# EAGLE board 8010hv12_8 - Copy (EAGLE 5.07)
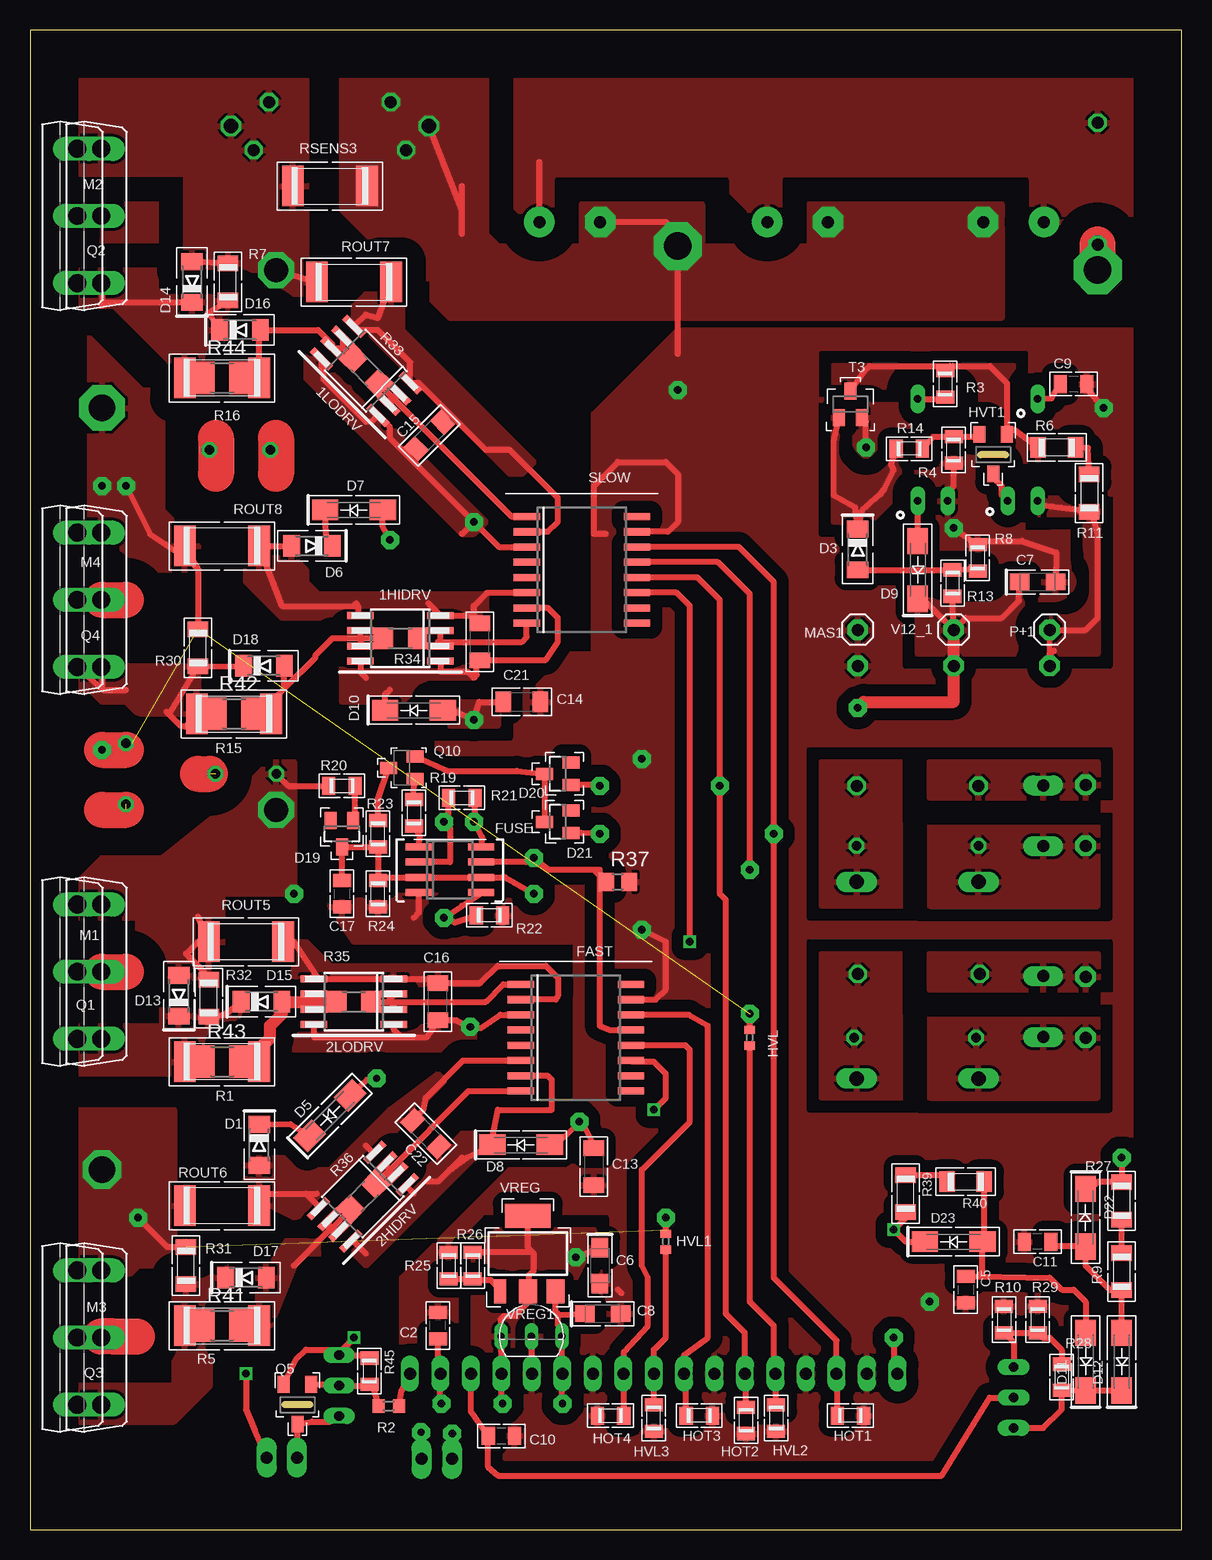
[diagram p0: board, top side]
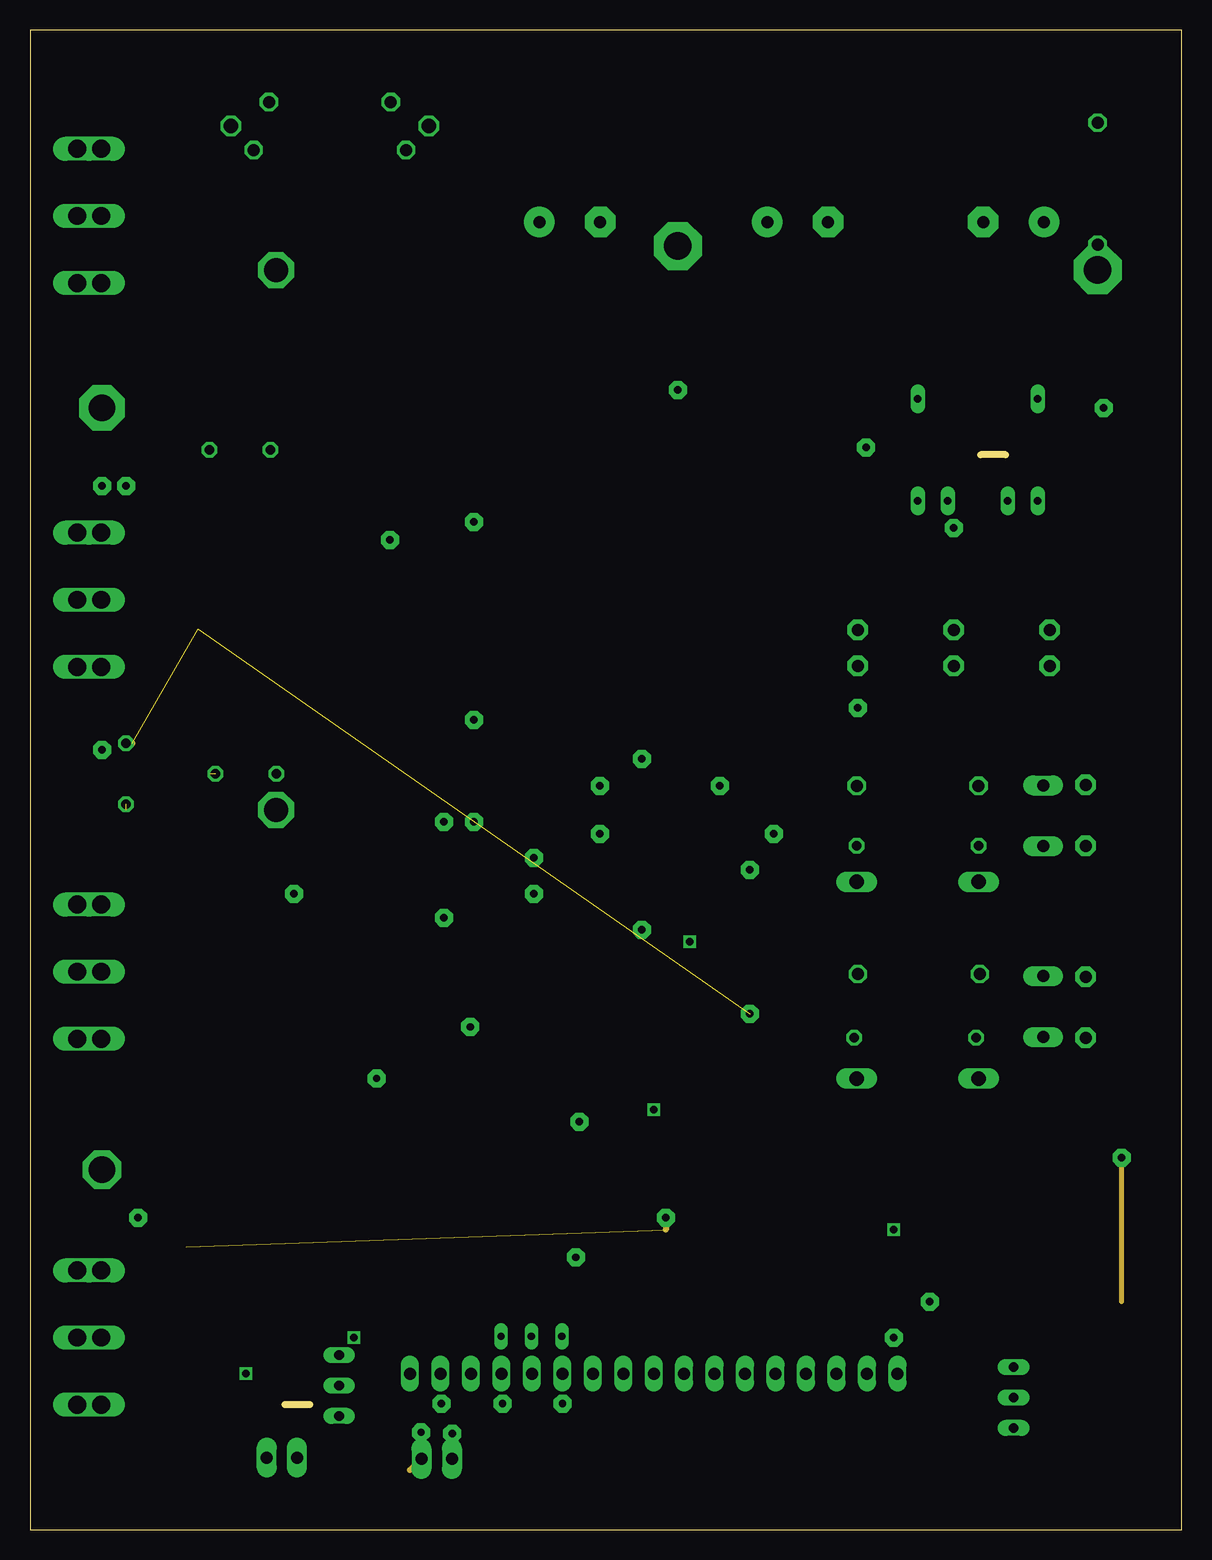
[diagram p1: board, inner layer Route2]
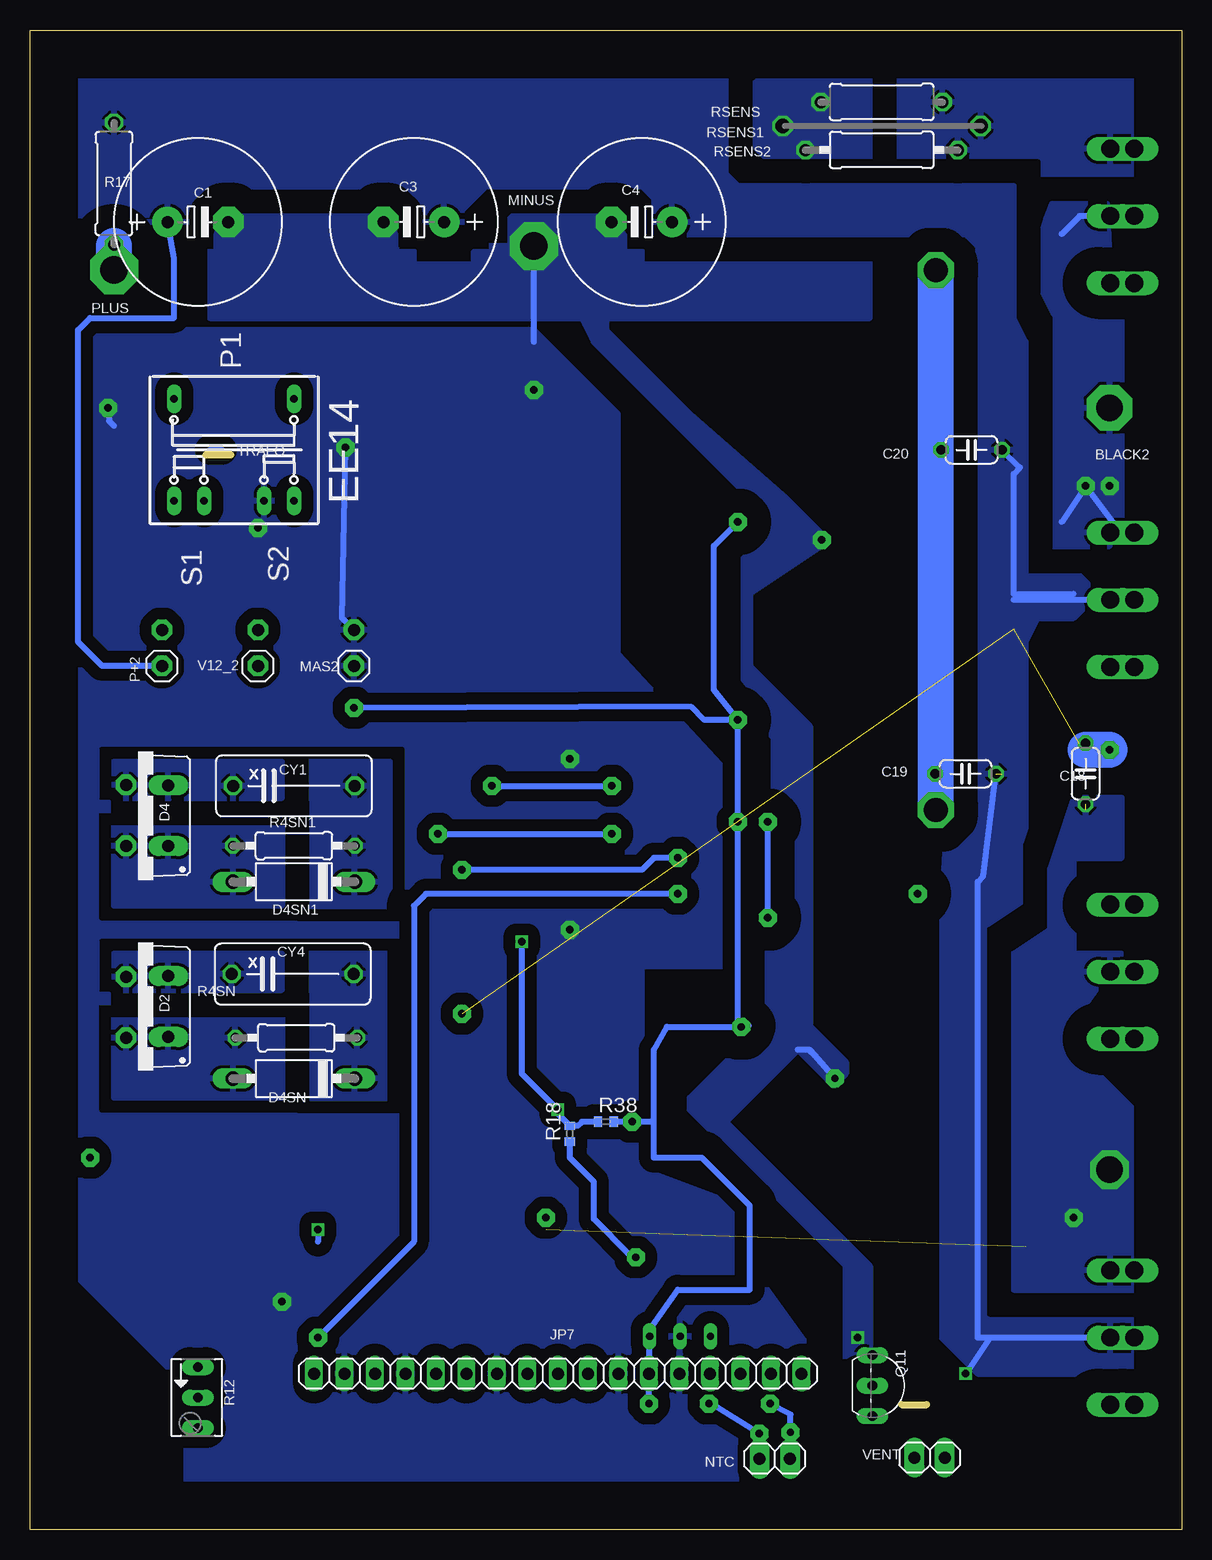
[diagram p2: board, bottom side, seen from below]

Size 96 x 125 mm. Coordinates in mm from the lower left corner, seen from the top.
Outline: 0,0 96,0 96,125 0,125 0,0
Copper layers (1*16): Top 0.035mm / dielectric 1.5mm / Bottom 0.035mm
Design rules "default *": minimum track width 10mil, minimum drill 20mil, track to track 8mil, track to pad 8mil, pad to pad 8mil, via to via 8mil, smd to smd 8mil, copper to edge 4mm, drill to drill 8mil, minimum pad ring 10mil, minimum via ring 8mil, stop-mask expansion 4mil, vias tented up to drill 0mil, thermal gap 10mil

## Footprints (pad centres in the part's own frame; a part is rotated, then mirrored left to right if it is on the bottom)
SO-08M = smd 0.6 x 2.2: 1 -1.905,-3.33; 2 -0.635,-3.33; 3 0.635,-3.33; 4 1.905,-3.33; 5 1.905,3.33; 6 0.635,3.33; 7 -0.635,3.33; 8 -1.905,3.33
1X2MM2 = drill 2.2 pad 3.81 octagon: 1 0,0
E5-13 = drill 1 pad 2.54 round: + -2.54,0 | drill 1 pad 2.54 octagon: - 2.54,0
C0805 = smd 1.1 x 1.5: 1 -1.1,0; 2 1.1,0
SMC_A = smd 1.6 x 1.4: + -1.5,0; - 1.5,0
C1206 = smd 1.3 x 1.7: 1 -1.55,0; 2 1.55,0
C050-024X044 = drill 0.8 octagon: 1 -2.54,0; 2 2.54,0
XC10B5 = drill 1 octagon: 1 -5.08,0; 2 5.08,0
MINIMELF = smd 1.4 x 1.8: A 1.7,0; C -1.7,0
TO220ACS = drill 1 pad 1.676 long: A 2.54,-2.54; C -2.54,-2.54
P1-10 = drill 1.2 long: A 5.08,0; C -5.08,0
SMA-DO214AC = smd 2.2 x 1.7: A 2.4,0; K -2.4,0
SOT23 = smd 1 x 1.4: 1 -0.95,-1.1; 2 0.95,-1.1; 3 0,1.1
SO16DW = smd 0.6 x 2.2: 1 -4.445,-4.6; 2 -3.175,-4.6; 3 -1.905,-4.6; 4 -0.635,-4.6; 5 0.635,-4.6; 6 1.905,-4.6; 7 3.175,-4.6; 8 4.445,-4.6; 9 4.445,4.6; 10 3.175,4.6; 11 1.905,4.6; 12 0.635,4.6; 13 -0.635,4.6; 14 -1.905,4.6; 15 -3.175,4.6; 16 -4.445,4.6
SO08 = smd 0.6 x 2.2: 1 -1.905,-2.6; 2 -0.635,-2.6; 3 0.635,-2.6; 4 1.905,-2.6; 5 1.905,2.6; 6 0.635,2.6; 7 -0.635,2.6; 8 -1.905,2.6
R0805 = smd 1.1 x 1.5: 1 -1.1,0; 2 1.1,0
R1005 = smd 0.7 x 0.9: 1 -0.65,0; 2 0.65,0
SOT23HV = smd 1 x 1.4: 1 -1.15,-1.7; 2 1.15,-1.7; 3 0,1.6
1X1MM0 = drill 1 pad 1.676 octagon: 1 0,0
1X17 = drill 1 long: 1 -20.32,0; 2 -17.78,0; 3 -15.24,0; 4 -12.7,0; 5 -10.16,0; 6 -7.62,0; 7 -5.08,0; 8 -2.54,0; 9 0,0; 10 2.54,0; 11 5.08,0; 12 7.62,0; 13 10.16,0; 14 12.7,0; 15 15.24,0; 16 17.78,0; 17 20.32,0
TO247BV = drill 1.499 long: D 0,-2.921; G -5.588,-2.921; S 5.588,-2.921
1X01 = drill 1 pad 1.676 octagon: 1 0,0
1X2MM3 = drill 2.3 pad 4 octagon: 1 0,0
1X02 = drill 1 pad 1.676 long: 1 -1.27,0; 2 1.27,0
SOT23-BEC = smd 1 x 1.4: B -0.95,-1.1; C 0,1.1; E 0.95,-1.1
TO92-EBC = drill 0.813 long: B 0,-1.27; C 2.54,-1.27; E -2.54,-1.27
R2512 = smd 1.8 x 3.4: 1 -3.1,0; 2 3.1,0
R0603 = smd 1 x 1.1: 1 -0.85,0; 2 0.85,0
0207/10 = drill 0.8 octagon: 1 -5.08,0; 2 5.08,0
R1206 = smd 1.3 x 1.7: 1 -1.55,0; 2 1.55,0
B64Y = drill 0.813 long: A 2.54,0; E -2.54,0; S 0,0
0309/10 = drill 1 octagon: 1 -5.08,0; 2 5.08,0
R0402 = smd 0.7 x 0.9: 1 -0.65,0; 2 0.65,0
R1206' = smd 1.6 x 1.803: 1 -1.422,0; 2 1.422,0
R0805' = smd 1.3 x 1.5: 1 -0.95,0; 2 0.95,0
R1210 = smd 1.6 x 2.7: 1 -1.4,0; 2 1.4,0
WIRE = drill 1.2 octagon: 1 -8.25,0; 2 8.25,0
0309/12 = drill 1 octagon: 1 -6.35,0; 2 6.35,0
SOT23' = smd 1 x 1.4: B -0.95,-1.1; C 0,1.1; E 0.95,-1.1
EE14 = drill 0.6 pad 1.2 long: 1 4.25,-5; 2 4.25,5; 3 -4.25,5; 4 -4.25,2.5; 5 -4.25,-2.5; 6 -4.25,-5
SOT223 = smd 1 x 2: 1 -2.3,-3.15 | smd 1.5 x 2: 2 0,-3.15; 3 2.3,-3.15 | smd 3.8 x 2: 4 0,3.15
TO92-2MIL = drill 0.6 pad 0.813 long: 1 -2.54,0; 2 0,0; 3 2.54,0

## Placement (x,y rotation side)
1HIDRV  MCP1407  [SO-08M]  30.88,74.29 90 top
1LODRV  MCP1407  [SO-08M]  28,96.59 45 top
2HIDRV  MCP1407  [SO-08M]  27.75,27.75 135 top
2LODRV  MCP1407  [SO-08M]  27,44 90 top
BLACK2  ACN  [1X2MM2]  6,93.5 180 bottom
C1  [E5-13]  82,109 0 bottom
C2  10n  [C0805]  34,17 90 top
C3  [E5-13]  64,109 180 bottom
C4  [E5-13]  45,109 180 bottom
C5  10n  [C0805]  78,20 270 top
C6  22u  [SMC_A]  47.5,22 270 top
C7  4u7  [SMC_A]  84,79 0 top
C8  22u  [SMC_A]  47.75,18 0 top
C9  331  [C0805]  87,95.5 0 top
C10  10n  [C0805]  39.3,7.8 0 top
C11  10n  [C0805]  84,24 180 top
C13  [C1206]  47,30.25 270 top
C14  [C1206]  41,69 0 top
C15  [C1206]  33.3,91.2 45 top
C16  [C1206]  34,44 90 top
C17  220p  [C0805]  26,53 270 top
C18  2n  [C050-024X044]  8,63 90 bottom
C19  10n  [C050-024X044]  18,63 180 bottom
C20  10n  [C050-024X044]  17.5,90 180 bottom
C21  [C1206]  37.5,74 90 top
C22  [C1206]  33,33 135 top
CY1  [XC10B5]  74,62 0 bottom
CY4  [XC10B5]  74.1,46.3 0 bottom
D1  Z15  [MINIMELF]  19.12,32.06 270 top
D2  [TO220ACS]  87,43.6 90 bottom
D3  BAT43  [MINIMELF]  69,81.7 270 top
D4  [TO220ACS]  87,59.5 90 bottom
D4SN  [P1-10]  74,37.6 180 bottom
D4SN1  [P1-10]  74,54 180 bottom
D5  M7  [SMA-DO214AC]  25,34.5 45 top
D6  Z15  [MINIMELF]  23.5,82 180 top
D7  M7  [SMA-DO214AC]  27,85 0 top
D8  [SMA-DO214AC]  40.93,32.07 0 top
D9  M7  [SMA-DO214AC]  74,80 90 top
D10  [SMA-DO214AC]  32,68.3 0 top
D11  M7  [SMA-DO214AC]  88,14 90 top
D12  M7  [SMA-DO214AC]  91,14 90 top
D13  Z15  [MINIMELF]  12.4,44.5 90 top
D14  Z15  [MINIMELF]  13.5,104 90 top
D15  4148  [MINIMELF]  19.3,44 0 top
D16  4148  [MINIMELF]  17.5,100 0 top
D17  4148  [MINIMELF]  18,21 0 top
D18  4148  [MINIMELF]  19.5,72 0 top
D19  [SOT23]  26,58 180 top
D20  [SOT23]  44,63 90 top
D21  [SOT23]  44,59 90 top
D22  M7  [SMA-DO214AC]  88,26 270 top
D23  M7  [SMA-DO214AC]  77,24 0 top
FAST  IR2110SO16  [SO16DW]  45.5,41 270 top
FUSE  LM393  [SO08]  35,55 270 top
HOT1  [R0805]  68.4,9.5 180 top
HOT2  [R0805]  59.7,9.1 90 top
HOT3  [R0805]  55.8,9.5 180 top
HOT4  [R0805]  48.4,9.5 0 top
HVL  [R1005]  60,41 90 top
HVL1  [R1005]  53,24 90 top
HVL2  [R0805]  62.2,9.3 270 top
HVL3  [R0805]  52,9.3 90 top
HVT1  A45HV  [SOT23HV]  80.3,89.6 180 top
JDRAIN  [1X1MM0]  88,41 270 top
JDRN1  [1X1MM0]  88,57 0 top
JP7  [1X17]  52,13 0 bottom
JSORC1  [1X1MM0]  88,62.08 0 top
JSOURCE  [1X1MM0]  88,46.08 270 top
M1  IRFP240  [TO247BV]  3,46.5 90 top
M2  IRFP240  [TO247BV]  3,109.5 90 top
M3  IRFP240  [TO247BV]  3,16 90 top
M4  IRFP240  [TO247BV]  3,77.5 90 top
MAS1  [1X01]  69,75 270 top
MAS2  [1X01]  69,72 90 bottom
MINUS  [1X2MM3]  54,107 270 bottom
NTC  ntc  [1X02]  33.9,5.9 180 bottom
P+1  [1X01]  85,75 270 top
P+2  [1X01]  85,72 90 bottom
PLUS  [1X2MM3]  89,105 270 bottom
Q1  IRFP240  [TO247BV]  1,46.5 90 top
Q2  IRFP240  [TO247BV]  1,109.5 90 top
Q3  IRFP240  [TO247BV]  1,16 90 top
Q4  IRFP240  [TO247BV]  1,77.5 90 top
Q5  847  [SOT23HV]  22.3,10.4 180 top
Q10  857  [SOT23-BEC]  31,63.5 90 top
Q11  A44  [TO92-EBC]  24.5,12 270 bottom
R1  1  [R2512]  16,39 180 top
R2  5k  [R0603]  29.9,10.3 180 top
R3  102  [R0805]  76.3,95.5 270 top
R4  7R5  [R0805]  77,90 90 top
R4SN  [0207/10]  73.8,41 0 bottom
R4SN1  [0207/10]  74,57 0 bottom
R5  1  [R2512]  16,17 0 top
R6  105  [R1206]  85.6,90.2 0 top
R7  15k  [R1206]  16.5,104 270 top
R8  103  [R0805]  79,81 270 top
R9  Rtop/2  [R1206]  91,21.5 90 top
R10  Rbot  [R0805]  81.2,17.5 270 top
R11  105  [R1206]  88.3,86.4 90 top
R12  pot  [B64Y]  82,11 270 bottom
R13  154  [R0805]  76.9,78.9 270 top
R14  821  [R0805]  73.3,90.1 180 top
R15  1  [R2512]  17,68 0 top
R16  1  [R2512]  16,96 180 top
R17  [0309/10]  89,112.2 90 bottom
R18  shrt  [R0402]  51,33 90 bottom
R19  68k  [R0805]  32,59.75 270 top
R20  510  [R0805]  26,62 0 top
R21  100k  [R0805]  36,61 0 top
R22  2k2  [R0805]  38.3,51.2 180 top
R23  100k  [R0805]  29,58 90 top
R24  4k7  [R0805]  29,53 90 top
R25  1k7  [R0805]  34.9,22 270 top
R26  3k3  [R0805]  36.9,22 270 top
R27  Rtop/2  [R1206]  91,27.4 90 top
R28  pot+  [R0805]  86,12.7 270 top
R29  Rbot+  [R0805]  84,17.5 270 top
R30  15k  [R1206]  14,73.5 270 top
R31  15k  [R1206]  13,22 270 top
R32  15k  [R1206]  14.9,44.3 270 top
R33  shrt  [R1206']  28,96.59 135 top
R34  shrt  [R1206']  30.88,74.29 180 top
R35  shrt  [R1206']  27,44 180 top
R36  shrt  [R1206']  27.75,27.75 225 top
R37  shrt  [R0805']  49,54 0 top
R38  shrt  [R0402]  48,34 0 bottom
R39  Rtop/2  [R1206]  73,28 270 top
R40  Rtop/2  [R1206]  78,29 180 top
R41  1  [R1210]  16,17 0 top
R42  1  [R1210]  17,68 0 top
R43  1  [R1210]  16,39 0 top
R44  1  [R1210]  16,96 0 top
R45  68k  [R0805]  28.3,13.2 270 top
ROUT5  [R2512]  18,49 180 top
ROUT6  [R2512]  16,27 180 top
ROUT7  [R2512]  27,104 0 top
ROUT8  [R2512]  16,82 180 top
RSENS  [WIRE]  25,117 180 bottom
RSENS1  [0309/10]  25,119 180 bottom
RSENS2  [0309/12]  25,115 180 bottom
RSENS3  [R2512]  25,112 0 top
SLOW  IR2110SO16  [SO16DW]  46,80 270 top
T3  A06  [SOT23']  68.4,93.8 0 top
TRAFO  EE14  [EE14]  79,90 90 bottom
V12_1  [1X01]  77,75 270 top
V12_2  [1X01]  77,72 90 bottom
VENT  vent  [1X02]  21,6 0 bottom
VREG  AP1117  [SOT223]  41.5,23 0 top
VREG1  LP2950  [TO92-2MIL]  41.8,16.1 0 top

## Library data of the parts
1HIDRV 1LODRV 2HIDRV 2LODRV = microchip
BLACK2 JDRAIN JDRN1 JP7 JSORC1 JSOURCE MAS1 MAS2 MINUS NTC P+1 P+2 PLUS V12_1 V12_2 VENT = pinhead
C1-C11 C13-C22 CY1 CY4 HOT1-HOT4 HVL HVL1-HVL3 R1-R4 R4SN R4SN1 R5-R8 R11 R13-R17 R19-R24 R30-R32 R45 ROUT5-ROUT8 RSENS RSENS1-RSENS3 = rcl
D1-D4 D4SN D4SN1 D5-D23 = diode
FAST SLOW = ir2112
FUSE = linear
HVT1 Q5 = transistor-npn
M1-M4 Q1-Q4 = transistor-power
Q10 = transistor-pnp
Q11 = transistor-neu-to92
R9 R10 R25-R29 R39-R44 = rcl-2
R12 = pot
R18 R33-R38 = rcl(2)
T3 = transistor
TRAFO = trafo
VREG VREG1 = v-reg

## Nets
1HO: D20.1 HOT2.2 JP7.6 SLOW.12
1LO: D21.1 HOT1.2 JP7.3 SLOW.14
2HO: FAST.12 HOT4.2 JP7.10
2LO: FAST.14 HOT3.2 JP7.8
A: D9.A TRAFO.6
ACL: D22.K R27.2
ACN: D23.K R39.2
B1C2: HVT1.1 R3.1 R6.1 T3.C
BLACK: BLACK2.1 C18.2 HVL.2 M2.D M4.S Q2.D Q4.S R30.1 ROUT8.2
BT1: D3.C R14.2 T3.B
C1: HVT1.3 TRAFO.4
COM1: 2LODRV.4 2LODRV.5 C16.2 FAST.2 ROUT5.1
COM2: 1LODRV.4 1LODRV.5 C15.2 ROUT7.2 SLOW.2
D1HO: 1HIDRV.2 1HIDRV.3 R34.1 SLOW.8
D1LO: 1LODRV.2 1LODRV.3 R33.1 SLOW.1
DFG: HVL1.1 HVL3.2 JP7.9
DIS: FUSE.1 R19.2
DR2: D4.C D4SN1.A JDRN1.1 R4SN1.1
DRAIN: D2.C D4SN.A JDRAIN.1 R4SN.1
EB: HVT1.2 R4.2 R14.1
GAT1: D13.C D15.C M1.G Q1.G R1.2 R32.2 R43.1
GAT1RD: 2LODRV.6 2LODRV.7 D15.A R1.1 R35.2 R43.2
GAT2: D14.C D16.C M2.G Q2.G R7.2 R16.2 R44.1
GAT2RD: 1LODRV.6 1LODRV.7 D16.A R16.1 R33.2 R44.2
GAT3: D17.C M3.G Q3.G R5.1 R31.2 R41.1
GAT3RD: 2HIDRV.6 2HIDRV.7 D17.A R5.2 R36.2 R41.2
GAT4: D18.C M4.G Q4.G R15.1 R30.2 R42.1
GAT4RD: 1HIDRV.6 1HIDRV.7 D18.A R15.2 R34.2 R42.2
IFB: C19.2 C20.2 D13.A D14.A M1.S M2.S Q1.S Q2.S R7.1 R20.1 R32.1 ROUT5.2 ROUT7.1 RSENS1.1 RSENS2.1 RSENS3.1 RSENS.1
IN+: PLUS.1 R17.1
JDH: HVL2.1 HVL.1 JP7.5
MASS: C1.- C2.2 C3.- C4.- C5.2 C6.- C7.- C8.- C9.2 C10.2 C11.2 C13.2 C14.2 C17.2 D5.A D7.A FAST.15 FUSE.4 HOT1.1 HOT2.1 HOT3.1 HOT4.1 HVL2.2 HVL3.1 JP7.2 JP7.4 JP7.7 JP7.11 JP7.13 MAS1.1 MAS2.1 MINUS.1 Q5.2 Q11.E R4.1 R8.1 R10.1 R22.1 R24.1 R25.1 R29.1 R37.2 R45.1 RSENS1.2 RSENS2.2 RSENS3.2 RSENS.2 SLOW.15 T3.E TRAFO.5 VREG1.2
N$1: Q5.3 Q11.C VENT.1
N$2: Q5.1 Q11.B R2.2 R45.2
N$3: JP7.17 R2.1
N$6: R3.2 TRAFO.1
N$7: C9.1 TRAFO.2
N$8: R6.2 R11.2
N$9: FUSE.2 FUSE.5 R21.1 R22.2
N$10: D3.A R8.2 R13.1
N$11: C11.1 D12.A D22.A R9.1
N$12: 2HIDRV.2 2HIDRV.3 FAST.8 R36.1
N$14: D19.1 R20.2
N$15: R39.1 R40.2
N$16: 2LODRV.2 2LODRV.3 FAST.1 R35.1
N$17: R25.2 R26.2 VREG.1
N$18: D20.3 D21.3 Q10.E
N$19: C5.1 D11.A D23.A R40.1
N$20: D1.C D5.K
N$23: R9.2 R27.1
N$24: D6.C D7.K
N$25: Q10.B R19.1
N$26: Q10.C R23.2
N$29: R10.2 R12.E R28.1 R29.2
N$30: D11.K D12.K R12.A R28.2
O_IFB: C17.1 D19.3 FUSE.3 FUSE.6 JP7.1 R23.1 R24.2
PUMP+: C1.+ C3.+ C4.+ C19.1 C20.1 M3.D M4.D P+1.1 P+2.1 Q3.D Q4.D R11.1 R17.2 TRAFO.3 VENT.2
RED: C18.1 HVL1.2 M1.D M3.S Q1.D Q3.S R31.1 ROUT6.2
SCR2: CY1.1 D4.A JSORC1.1
SD: FAST.13 FUSE.7 R37.1 SLOW.13
SNUB1: CY1.2 D4SN1.C R4SN1.2
SNUB2: CY4.2 D4SN.C R4SN.2
SOURCE: CY4.1 D2.A JSOURCE.1
TFB: C2.1 JP7.16 NTC.1
V12: 1LODRV.1 1LODRV.8 2LODRV.1 2LODRV.8 C7.+ C8.+ C13.1 C14.1 C15.1 C16.1 D8.A D9.K D10.A FAST.3 FUSE.8 JP7.12 R13.2 R21.2 R38.2 SLOW.3 V12_1.1 V12_2.1 VREG1.3 VREG.3
VB1: 1HIDRV.1 1HIDRV.8 C21.1 D10.K SLOW.7
VB2: 2HIDRV.1 2HIDRV.8 C22.1 D8.K FAST.7
VDD: C6.+ JP7.14 NTC.2 R18.1 R26.1 VREG1.1 VREG.4
VDD1: FAST.11 R18.2 R38.1 SLOW.11
VFB: C10.1 JP7.15 R12.S
VS3: 2HIDRV.4 2HIDRV.5 C22.2 D1.A FAST.6 ROUT6.1
VS4: 1HIDRV.4 1HIDRV.5 C21.2 D6.A ROUT8.1 SLOW.6

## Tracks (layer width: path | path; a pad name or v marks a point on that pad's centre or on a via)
1HO  (via drill 0.6 pad 1.5)
  Top 0.5: D20.1 46.95,62.05 v47.5,62 | HOT2.2 59.7,12.92 JP7.6 59.6,14.4 59.6,16.4 58,18 58,52.5 57.5,53 v57.5,62 57.5,73 57.5,77.5 56,79 55.63,79.36 SLOW.12
  Bottom 0.5: v57.5,62 v47.5,62
1LO  (via drill 0.6 pad 1.5)
  Top 0.5: D21.1 46,58.05 v47.5,58 | HOT1.2 67.3,12.94 JP7.3 67.24,15.76 62,21 v62,58 62,79 59.09,81.91 SLOW.14
  Bottom 0.5: v62,58 v47.5,58
2HO
  Top 0.5: HOT4.2 49.5,12.96 JP7.10 49.5,14.8 51.5,17 51.5,21 51,22 51,30 55,34 55,40 54.63,40.37 FAST.12
2LO
  Top 0.5: HOT3.2 54.7,12.84 JP7.8 54.54,14.54 56.5,16 56.5,42 54.91,42.91 FAST.14
A
  Top 0.5: D9.A TRAFO.6
ACL  (via drill 0.6 pad 1.5)
  Top 0.5: v91,31 R27.2 90.95,29 89,29 88.4,28.4 D22.K
  Route2 0.406: 91,19 v91,31
ACN  (via drill 0.6)
  Top 0.5: R39.2 73,26 v72,25 73,24 D23.K
  Bottom 0.5: v72,25 72,24
B1C2
  Top 0.5: R6.1 82.05,91.7 HVT1.1 81.45,95.55 80,97 76.9,97 | 76.7,97 R3.1 76.9,97 | T3.C 69.6,96.6 70,97 76.7,97 | 76.7,97 76.9,97
  pour Top (isolate 2): 82,92 82,97 67,97 67,94 80,94 80,92 83,89 85,89 85,91
BLACK  (via drill 0.6 pad 1.5)  (2 unrouted)
  Top 0.5: Q4.S M4.S | v8,87 10,83 13,81 14,80.1 | 14,80.1 ROUT8.2 | HVL.2 v60,43 | 14,80.1 R30.1
  Route2 0.5: C18.2 8.54,65.54
  Bottom 0.5: M2.D 8.5,109.5 10,108 | 10,84 v8,87 5,83
  other vias: 6,87
  pour Bottom (isolate 2, rank 3): 6.2,110.5 10.8,110.5 arc-41 11.4,100.5 11,100 11,82 6,82 6,83 5,84 5,105 6,106
  pour Top (isolate 2, rank 3): 6.2,110.5 10.8,110.5 arc-41 11.4,100.5 11,100 11,85 14,82 14,80 10,80 6,83 5,84 5,105 6,106
BT1
  Top 0.5: T3.B 67,90.75 67,86.2 68.8,85.2 D3.C 69.4,85 70.9,86.3 71.2,86.7 72,88.3 71.8,88.8 R14.2
  pour Top (isolate 1.5, rank 2): 74,90 74,88 70,84 67,84 67,93 69,93 69,92 71,90
C1
  Top 0.5: HVT1.3 80.3,87.7 81,87 81,86.25 TRAFO.4
COM1
  Top 0.5: ROUT5.1 22,49 24,46 23.77,46 2LODRV.5 29.91,45.91 30,46 30.23,46 2LODRV.4 34.65,45.91 C16.2 37.55,45.55 39,47 43,47 44,46 44,44.5 43.83,44.17 FAST.2
  pour Top (isolate 1): 22,49 23,49 25,47 39,47 39,45 37,45 23,45 22,46 22,48
COM2
  Top 0.5: 35,93 38,90 40,90 44,86 44,84 43.17,83.17 SLOW.2 | 35,93 32.42,95.58 1LODRV.4 31.7,97.3 29,100 27.28,100 1LODRV.5 28,101.28 29,101 ROUT7.2 | C15.2 34.4,92.4 35,93
  pour Top (isolate 1): 31,103 31,100 42,89 41,88 40,88 27,101 27,102 28,103
D1HO
  Top 0.5: R34.1 33.06,73.66 1HIDRV.2 | 1HIDRV.2 1HIDRV.3 | SLOW.8 41.4,74.4 41,74 34,74 34,73.87 1HIDRV.2
D1LO
  Top 0.5: 30.12,94.46 29.84,94.75 R33.1 40.14,84.44 SLOW.1 | 1LODRV.3 30.59,94.46 30.12,94.46 | 1LODRV.2 30.12,94 30.12,94.46
DFG
  Top 0.5: HVL1.1 53,16 52,15 JP7.9 HVL3.2
DIS
  Top 0.5: R19.2 32.5,57.8 FUSE.1
DR2
  pour Top (isolate 2, rank 2): 89,59 75,59 75,52 89,52
  pour Bottom (isolate 2, rank 2): 89,59 75,59 75,52 89,52
DRAIN
  pour Top (isolate 2, rank 2): 89,43 75,43 75,36 89,36
  pour Bottom (isolate 2, rank 2): 89,43 75,43 75,36 89,36
EB
  Top 0.5: R14.1 75.3,91.1 R4.2 78.95,91.1 HVT1.2
GAT1
  Top 0.5: R32.2 16.25,42.95 D15.C | Q1.G M1.G
  Top 1: R43.1 R1.2
  pour Top (isolate 2): 3,42 11,42 11,44 18,44 16,38 3,38
GAT1RD
  Top 0.5: 25,44 R35.2 | 25,44 24.3,44 2LODRV.7 | 2LODRV.6 24.36,44.63 25,44
  Top 1: R35.2 25,44 D15.A 21,43 20,42 20,41 19.1,40.1 R1.1 R43.2
GAT2
  Top 0.5: R7.2 14.85,101.45 D16.C | D14.C 6.3,102.3 6,102 6,104 6.07,104 M2.G | R44.1 R16.2
  pour Top (isolate 2, rank 2): 2,105 11,105 18,103 18,97 12,97 7,102 2,102
GAT2RD
  Top 0.5: 26.09,98.49 R33.2 | 26.09,98.49 1LODRV.7 25.2,98.8 24,100 D16.A 19.1,100 R16.1 R44.2 | 26.09,98.49 1LODRV.6
GAT3
  pour Top (isolate 2, rank 3): 3,12 3,9 12,9 15,12 15,18 17,22 12,20 12,12
GAT3RD
  Top 0.5: 22,22 24.95,24.95 | 24.95,24.95 2HIDRV.6 | 24.95,24.95 25,25 | 25,25 R36.2 | 2HIDRV.7 25.05,24.95 25,25 | R41.2 R5.2
  pour Top (isolate 1.5, rank 2): 22,25 29,28 26,23 23,23 22,22 20,17 19,17 19,22 20,22
GAT4
  Top 0.5: Q4.G 6.07,70 | 6.07,70 8,70 | 11.62,67.95 R30.2 14.75,71.95 D18.C | 11.62,67.95 11.39,68.18 | 11.62,67.95 12.57,67 13,67 12.9,66.9 R15.1 R42.1 | 6.07,70 6.07,71.76 M4.G
  pour Top (isolate 1.5): 2.9,72.5 6.9,72.5 8,72 14,72 14,68 9,68 8,69 6,69 5,70 3,70
GAT4RD
  Top 0.5: 27.55,74.29 1HIDRV.7 | 27.55,74.29 1HIDRV.6 | 27.55,74.29 25.22,74.29 23.81,72.88 23.81,72.71 21.2,70.1 | 20.1,69 R15.2 R42.2 | 20.1,69 20.1,69.1 | 27.55,74.29 R34.2 | 21.2,70.1 D18.A | 20.1,69 21.2,70.1
IFB  (via drill 0.6 pad 1.5, 2 pad 1.5)
  Top 0.5: D14.A 14.35,105.7 R7.1 | 14,51.1 ROUT5.2 14,49 13,48 14.5,46.5 R32.1 | v20.5,105 ROUT7.1 | 20.5,91 20.5,90.46 C20.2 | R20.1 21.54,62 C19.2
  Top 3: 20.5,91 20.5,88
  Bottom 0.5: v20.5,105 20.5,90.46 C20.2
  Bottom 3: v20.5,60 v20.5,105
  other vias: 22,53
  pour Top (isolate 2, rank 2): 3,51 3,54 4,54 6,56 11,56 16,60 20,64 22,64 22,53 16,53 16,46 9,46 9,51
  pour Top (isolate 2): 3,121 23,121 23,103 22,103 19,105 13,105 13,113 4,113 3,114
  pour Bottom (isolate 2, rank 4): 3,121 24,121 24,113 4,113 3,114
IN+
  Top 3: PLUS.1 R17.1
  Bottom 3: PLUS.1 89,107
JDH
  Top 0.5: HVL.1 60,19 62,17 62,13.16 JP7.5 62.2,12.96 HVL2.1
MASS  (via drill 0.6, 0.6 pad 1.5)
  Top 0.5: C7.- 85.55,81.45 82.7,82.4 79.8,82.4 R8.1 78.9,82.1 v77,83.5 | C9.2 88.1,95.1 v89.5,93.5 | TRAFO.5 76.5,86.5 77,87 R4.1 | v69.7,90.2 69.7,92.35 T3.E | 36,110 36,112 | 47,109 C4.- 53,109 54,108 54,98 | 36,108 36,110 | 36,110 RSENS.2 | 49,20 49.3,19.7 | FUSE.4 32.4,51.4 32,51 | FAST.15 52.17,44.17 53,45 53,49 v51,50 | D7.A 29.4,83.6 v30,82.5 | SLOW.15 53.17,83.17 54,84 54,88 53,89 49,89 47,87 47,83 48,83 | D5.A 28.1,37.5 v28.9,37.6 | JP7.13 41.84,16.06 VREG1.2 | v27,16 26.73,15.73 | Q5.2 22.15,14.15 23,15 26,15 v27,16 | v27,16 26.77,15.77 Q11.E 28.06,14.54 R45.1
  Bottom 0.5: v69.7,90.2 70,76 MAS1.1 | v89.5,93.5 89.4,92.4 89,92 | v77,83.5 77,83 | v28.9,37.6 30.57,39.5 | 30.57,39.5 31,40 | 54,99 MINUS.1 | 32,40 31.06,40 30.57,39.5
  other vias: 51,64.25 54,95 75,19
  pour Bottom (isolate 2): 90,97 90,73 67,73 67,97
  pour Top (isolate 2, rank 5): 90,97 90,73 67,73 67,97
  pour Bottom (isolate 1, rank 4): 35,60 47,73 47,93 54,100 93,100 93,22 83,12 83,4 23,4 36,22 37,27 45,30 45,47 34,47
  pour Top (isolate 1, rank 4): 47,93 54,100 94,100 92,23 82,4 31,4 31,21 40,30 45,30 45,34 45.5,34 45.5,49 27,49 25,52 36,69 37,70 42,70 45,73 47,73
  pour Bottom (isolate 2, rank 3, no thermals): 26,101 26,121 35,121 38,119 38,108 39,107 45.8,107 48,110 56,110 56,107 65,107 65,110 80,110 81,109 81,101
  pour Top (isolate 2, rank 2, no thermals): 26,121 38,121 38,108 39,107 46,107 46,110.5 56,110.5 56,107 65,107 65,110.5 81,110.5 81,101 35,101 26,110
  pour Bottom (isolate 2): 26,22 26,14 28,14 28,22 41,35 41,36 37,40 37,46 34,49 34,66 38,70 38,81 37,82 36,86 49,99 50,101 48,103 48,100 41,93 33,86 30,83 30,82 36,78 36,72 31,67 31,42 28,39 28,38 29,37 32,40 38,34
N$1
  Top 0.5: VENT.1 22.3,7.03 Q5.3 23.5,9 25,9 25.46,9.46 Q11.C
N$2
  Top 0.5: Q5.1 26.67,12.1 Q11.B 28.55,12 | 28.55,12 R2.2 | 28.55,12 28.4,12 R45.2
N$3
  Top 0.5: R2.1 30.98,11.6 JP7.17
N$4
  Bottom 0.5: 80,90 81,90
N$6
  Top 0.5: TRAFO.1 75.95,94.25 R3.2
N$7
  Top 0.5: C9.1 85.15,94.3 TRAFO.2
N$8
  Top 0.5: R11.2 88.2,90.15 R6.2
N$9  (via drill 0.6 pad 1.5)
  Top 0.5: R21.1 34.9,59.1 34.8,59 v34.5,59 35,58.5 35,55.63 FUSE.2 | FUSE.5 37.51,53 36,52 v34.5,51 35.4,50.6 R22.2
  Bottom 0.5: v34.5,51 v34.5,59
N$10
  Top 0.5: R8.2 78.8,80.1 R13.1 D3.A
N$11
  Top 0.5: D12.A R9.1 90.05,19.95 88,22 D22.A 85.5,23.6 C11.1
N$12
  Top 0.5: FAST.8 36.55,36.55 30,30 | 29.66,29.66 30,30 | 2HIDRV.3 29.66,30.34 30,30 | 29.66,29.66 2HIDRV.2 | R36.1 29.66,29.66
N$13  (via drill 0.6 pad 1.5)
  Top 3: v6,65 8,65
  Bottom 3: v6,65 8,65
N$14
  Top 0.5: R20.2 27.1,59.25 D19.1
N$15
  Top 0.5: R39.1 75.9,29.55 R40.2
N$16
  Top 0.5: 30,44 30,44.2 | 30,44.2 29.9,43.97 | 2LODRV.2 30.33,43.67 30,44 | 30,44.2 30,44 | 2LODRV.3 30.33,44.53 30,44.2 | R35.1 30,44 | FAST.1 39.45,45.45 38,44 30,44
N$17
  Top 0.5: R25.2 R26.2 37.1,20.8 38.4,20.8 39.2,20 VREG.1
N$18
  Top 0.5: Q10.E 34.8,63.25 40.6,63.25 D20.3 D21.3
N$19
  Top 0.5: D11.A 88,19 87,20 86,20 85,21 79,21.09 | C5.1 79,21.09 | R40.1 79.55,24.15 D23.A 79.4,21.48 79,21.09
N$20
  Top 0.5: D1.C 21.7,33.8 D5.K
N$23
  Top 0.5: R9.2 R27.1
N$24
  Top 0.5: D6.C 24.7,82.9 D7.K
N$25
  Top 0.5: Q10.B 31.95,61.05 R19.1
N$26
  Top 0.5: R23.2 29,60.9 Q10.C
N$29
  Top 0.5: R28.1 86,15 85,16 84.4,16 R29.2 R10.2 82,15.6 R12.E
N$30
  Top 0.5: R12.A 84.46,8.46 86,10 R28.2 D11.K D12.K
O_IFB  (via drill 0.6 pad 1.5)
  Top 0.5: C17.1 D19.3 R23.1 R24.2 29.27,54.37 FUSE.3 FUSE.6 39.63,54.37 v42,53 | v72,16 72,13.32 JP7.1
  Bottom 0.5: v42,53 63,53 64,52 64,24 v72,16
PUMP+  (via drill 0.6)  (1 unrouted)
  Top 0.406: P+2.1 P+1.1
  Top 0.5: P+1.1 88,75 89,76 89,83 88.65,84.35 R11.1 84.4,85.35 TRAFO.3 | P+2.1 85,73 85.38,73.27 | C4.+ 42.46,114 | Q4.D M4.D 6,77.5 8,77.5 | M3.D 6.9,16 7,16.1 | C20.1 14.96,90.46 15.5,91 | v18,13 18,10 18.73,8.27 VENT.2
  Top 3: 15.5,91 15.5,88 | 6,77.5 8,77.5 | 5.9,16.1 7,16.1 8.9,16.1 | 14,63 15,63
  Bottom 0.5: C1.+ 84,106 84,101 91,101 92,100 92,74 90,72 P+2.1 | 14,78 14,88 13.46,88.54 C20.1 | 14,78 9,78 | 11,77.5 14,77.5 | M4.D 11,77.5 | 11,77.5 14,78 | M3.D 16,16 | 16,16 17,16 17,54 16.54,54.46 C19.1 | 16,16 v18,13
  pour Top (isolate 2, rank 2): 89,86 89,73 85,73 85,77 88,77 88,84.6 84,84.6 84,86
  pour Bottom (isolate 2, rank 2): 38,121 92,121 92,108 83,108 79,112 66,112 63,109 63,108 60,108 60,110 58,112 45,112 44,111 44,108 18,108 17,107 17,84 13,84 13,99 14,101 14,112 37,112 38,113
  pour Top (isolate 2, rank 4): 40,121 92,121 92,108 83,108 79,112 66,112 63,109 63,108 60,108 60,110 58,112 45,112 44,111 44,108 17,108 16,107 11,109 14,112 37,112 38,113
  pour Bottom (isolate 2, rank 4): 3,18 13,18 13,74 12,76 9,76 7,78 9,80 12,80 13,81 13,90 14,91 15,91 18,88 20,52 20,16 17,13 4,13 3,14
RED  (via drill 0.6 pad 1.5, 2.2 pad 1.5)  (2 unrouted)
  Top 0.5: HVL1.2 v53,26 | R31.1 11.45,23.55 v9,26 | Q1.D M1.D 6,46.5
  Top 3: 6,46.5 8,46.5 | 6,60 8,60
  Route2 0.5: v53,26 53,25
  other vias: 6,30
  pour Top (isolate 2): 4,21 4,35 12,35 12,24 13,24 11,22 9,22 8,21
  pour Bottom (isolate 2): 5,61 9,61 11,55 11,50 14,48 14,20 4,20 4,35 10,41 5,48 9,48 9,56 5,56
SCR2
  pour Top (isolate 2): 89,64 89,61 75,61 75,64
  pour Bottom (isolate 2): 89,64 89,61 75,61 75,64
SD  (via drill 0.6 pad 1.5)
  Top 0.5: FAST.13 48.37,41.63 47.5,42 47.5,55 47,55 | 47,55 43.27,55 42.27,55.73 v42,56 41.37,55.63 FUSE.7 | SLOW.13 57.37,80.64 60,78 v60,55 | R37.1 48,54 47,55
  Bottom 0.5: v42,56 44,56 45,55 v60,55
SNUB1
  pour Top (isolate 2, rank 3): 73,64 73,52 66,52 66,64
  pour Bottom (isolate 2, rank 3): 73,64 73,52 66,52 66,64
SNUB2
  pour Top (isolate 2, rank 3): 73,48 73,36 66,36 66,48
  pour Bottom (isolate 2, rank 3): 73,48 73,36 66,36 66,48
SOURCE
  pour Top (isolate 2): 89,48 89,45 75,45 75,48
  pour Bottom (isolate 2): 89,48 89,45 75,45 75,48
TFB  (via drill 0.6 pad 1.5)
  Top 0.5: C2.1 34,13.22 JP7.16 34.2,10.78 v34.3,10.5 | NTC.1 32.63,7.63 v32.6,8.1
  Route2 0.5: 31.68,4.95 NTC.1
  Bottom 0.5: v32.6,8.1 32.6,9.6 v34.3,10.5
V12  (via drill 0.6 pad 1.5)
  Top 0.406: 43.4,31.5 43.4,31.6 v45.8,34
  Top 0.5: C7.+ 82.45,77.45 81,76 78,76 V12_1.1 | V12_1.1 R13.2 | D9.K 74,78 V12_1.1 | 31,41 33,41 C16.1 35.55,42.45 v36.7,41.9 37.6,41.8 39.2,42.9 39.7,42.91 FAST.3 | 31,41 24,41 | 24,41 23.7,41 | FUSE.8 37.7,57.7 v37,59 37.1,59.6 R21.2 | v44.4,10.5 44.3,12.92 JP7.12 | JP7.12 44.2,13.18 | JP7.12 44.34,13.04 VREG1.3 44.3,16.14 44.3,16.8 44,17.1 44,18 | 2LODRV.8 23.67,41.33 24,41 | 2LODRV.1 30.33,41.67 31,41 | 1LODRV.8 24.3,96.89 24.46,96.73 24.46,95.88 27.29,93.05 28,92.34 28.47,92.34 1LODRV.1 30,91.89 30,91 31.5,89.5 | VREG.3 43.8,18.2 44,18 | C8.+ 44.1,17.9 44,18 | D8.A 43.4,31.5 43.9,31.5 43.9,31.7 | SLOW.3 39.09,81.91 v37,84 | v37,84 31.5,89.5 | C15.1 32.1,90.1 31.5,89.5 | C13.1 47,32 46,34 46,33.4 v45.8,34 | D10.A 34.4,68.6 v37,67.5 37.45,69 C14.1 | v37,84 36,83 v37,84
  Top 1: v69,68.5 69.5,69 77,69 V12_2.1 V12_1.1
  Bottom 0.5: v37,67.5 v37,59 37,42 | v37,67.5 39,70 39,82 v37,84 | v36.7,41.9 37,42 | v37,67.5 39.8,67.5 40.9,68.6 v69,68.5 | v44.4,10.5 44.3,16.8 44.1,17 42,20 36,20 36,27 40,31 44,31 44,34 | v36.7,41.9 36.1,42 37,42 | v36.7,41.9 42.9,41.9 44,40 44,34 | 44,34 v45.8,34 R38.2
  pour Top (isolate 2): 83,79 83,73 74,73 74,78 81,78
  pour Top (isolate 1): 23,98 23,96 36,83 37,83 38,84 24,98
  pour Top (isolate 1.5): 35,69 39,69 39,67 35,67
  pour Top (isolate 1.5): 23,42 37,42 37,40 22,40 22,42
VB1
  Top 0.5: SLOW.7 43.17,76.83 44,76 44,74 43,72.5 37.5,72.5 C21.1 37.24,71.89 37.24,71.24 37,71 36.49,71.51 34.21,71.51 1HIDRV.1 | 1HIDRV.8 27.55,71.45 28,71 | D10.K 29.6,69.6 30,70
  pour Top (isolate 1.5, rank 2): 26,72 37,72 37,71 33,71 31,69 26,69
VB2
  Top 0.5: 33.18,29 34,29 35,30 | 35,30 36,31 35.99,31.01 | 35,30 36.4,31 D8.K 38.5,32.5 39,35 43.5,35 43.5,37.5 43.2,37.8 42.83,37.83 FAST.7 | 2HIDRV.1 31.45,28.55 32,28 | 2HIDRV.8 26.95,24.05 28,23
  pour Top (isolate 1.5): 27,23 28,22 37,31 37,33 36,33 27,24
VDD  (via drill 0.6 pad 1.5)
  Top 0.5: 41.9,23.1 R26.1 | 41.9,23.1 42,23 42,21.6 41.6,21.2 41.6,19 40.4,17.8 39.5,17.8 39.26,17.56 VREG1.1 39.3,16.06 JP7.14 39.3,11.3 v39.4,10.5 | VREG.4 41.5,23.5 41.9,23.1 | v35.2,8 35,6.07 NTC.2 | v45.5,22.7 C6.+
  Bottom 0.5: v39.4,10.5 39.4,10.6 v35.2,8 | R18.1 51,31 49,29 49,25.88 46.03,22.91 45.71,22.91 v45.5,22.7
  pour Top (isolate 0.8): 39,25 47,25 47,24 45,20 43,20 43,19 40,15 37,15 37,23
VDD1  (via drill 0.6)
  Top 0.5: SLOW.11 53.91,78.09 55,77 v55,49 | v52,35 53,36 53,38 52,39 51,39 50.2,39 FAST.11
  Bottom 0.5: v55,49 55,38 v52,35 52,34.65 R18.2 50.35,33.65 50,34 R38.1
VFB
  Top 0.5: R12.S 80,11 76,4.5 39,4.5 38.2,5.2 C10.1 36.76,9.84 JP7.15
VS3
  Top 0.5: ROUT6.1 19.25,28.1 | 19.25,28.1 19.3,28.51 | 2HIDRV.4 28.55,31.45 28,32 | FAST.6 36.09,39.09 33,36 32.81,35 C22.2 | 2HIDRV.5 24.05,26.95 23,28 | 23,28 23.9,28 | 23,28 19.35,28 19.25,28.1
  pour Top (isolate 1.5): 18,31 23,31 24,30 25,30 30,35 34,38 35,37 25,27 22,26 18,28
VS4
  Top 0.5: 1HIDRV.5 27.34,76.4 27.34,77 27,77 | SLOW.6 38.09,78.09 37,77 37,76.2 | 37,76.2 C21.2 | 27,77 21,77 ROUT8.1 D6.A | 37,76.2 1HIDRV.4 33.21,77.19 | 27,77 27.19,77.19
  pour Top (isolate 1.5): 18,81 22,81 23,80 23,79 24,78 38,78 38,76 21,76 18,79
